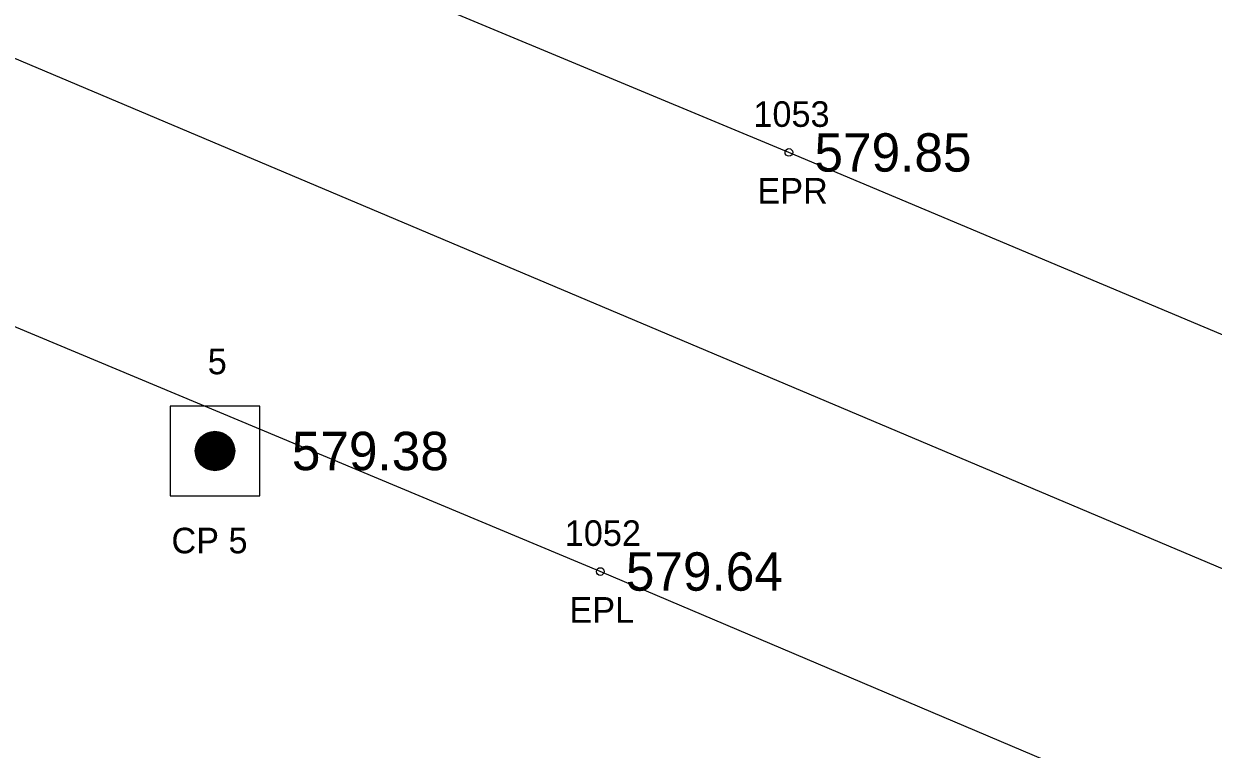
# Model space of a CAD drawing. Extents: x 1664393 to 1667175, y 987029 to 988607.
# Drawn here: x 1665718.92 to 1665765.38, y 987649.18 to 987677.54 of the extents above; entities that cross this region are included whole.
import ezdxf

# ---------------------------------------------------------------- set-up
doc = ezdxf.new("R2010")
doc.units = 0
for name, color, linetype in [('RD_EX_Road', 7, 'Continuous'), ('RD_EX_Road_txCode', 7, 'Continuous'), ('RD_EX_TX_Road_ELEV', 7, 'Continuous'), ('RD_HC_Cl', 7, 'Continuous'), ('RD_HC_Survey', 7, 'Continuous'), ('RD_HC_Survey_ELEV', 7, 'Continuous'), ('RD_HC_Survey_txCode', 7, 'Continuous'), ('RD_SMD_Locator', 7, 'Continuous')]:
    doc.layers.add(name, color=color, linetype=linetype)

msp = doc.modelspace()

# ---------------------------------------------------------------- linework, layer by layer
at = {"layer": 'RD_EX_Road'}
for points in [[(1666163.185, 987497.623), (1666116.595, 987517.386), (1666070.703, 987536.94), (1666024.42, 987556.434), (1665979.015, 987575.668), (1665932.354, 987595.551), (1665886.935, 987614.539), (1665839.872, 987634.254), (1665794.504, 987653.269), (1665748.805, 987672.511), (1665702.363, 987691.865), (1665656.419, 987711.451), (1665610.33, 987731.033), (1665564.854, 987750.933), (1665531.474, 987764.82)], [(1666156.674, 987480.61), (1666109.284, 987500.741), (1666063.55, 987520.043), (1666017.041, 987539.822), (1665971.114, 987559.142), (1665924.884, 987578.792), (1665879.498, 987597.891), (1665833.217, 987617.382), (1665786.906, 987636.812), (1665741.438, 987656.129), (1665695.815, 987675.204), (1665649.264, 987694.848), (1665603.559, 987714.712), (1665558.4, 987733.869), (1665524.706, 987748.932)]]:
    msp.add_lwpolyline(points, dxfattribs=at)
at = {"layer": 'RD_HC_Cl'}
msp.add_line((1666160.052, 987489.414), (1664963.07, 987995.795), dxfattribs=at)
at = {"layer": 'RD_HC_Survey'}
for p, q in [((1665725.763, 987660.39), (1665725.763, 987661.289)), ((1665725.788, 987660.358), (1665725.788, 987661.322)), ((1665725.813, 987660.328), (1665725.813, 987661.351)), ((1665725.837, 987660.302), (1665725.837, 987661.377)), ((1665725.862, 987660.278), (1665725.862, 987661.402)), ((1665725.887, 987660.255), (1665725.887, 987661.424)), ((1665725.912, 987660.235), (1665725.912, 987661.444)), ((1665725.936, 987660.216), (1665725.936, 987661.463)), ((1665725.961, 987660.199), (1665725.961, 987661.48)), ((1665725.986, 987660.183), (1665725.986, 987661.496)), ((1665726.011, 987660.169), (1665726.011, 987661.51)), ((1665726.035, 987660.156), (1665726.035, 987661.524)), ((1665726.06, 987660.143), (1665726.06, 987661.536)), ((1665726.085, 987660.132), (1665726.085, 987661.547)), ((1665726.11, 987660.122), (1665726.11, 987661.557)), ((1665726.134, 987660.113), (1665726.134, 987661.566)), ((1665726.159, 987660.105), (1665726.159, 987661.574)), ((1665726.184, 987660.098), (1665726.184, 987661.582)), ((1665726.209, 987660.091), (1665726.209, 987661.588)), ((1665726.233, 987660.086), (1665726.233, 987661.593)), ((1665726.258, 987660.081), (1665726.258, 987661.598)), ((1665726.283, 987660.077), (1665726.283, 987661.602)), ((1665726.308, 987660.074), (1665726.308, 987661.605)), ((1665726.332, 987660.072), (1665726.332, 987661.607)), ((1665726.357, 987660.071), (1665726.357, 987661.608)), ((1665726.382, 987660.07), (1665726.382, 987661.609)), ((1665726.407, 987660.07), (1665726.407, 987661.609)), ((1665726.431, 987660.071), (1665726.431, 987661.608)), ((1665726.456, 987660.073), (1665726.456, 987661.606)), ((1665726.481, 987660.076), (1665726.481, 987661.603)), ((1665726.506, 987660.079), (1665726.506, 987661.6)), ((1665726.53, 987660.083), (1665726.53, 987661.596)), ((1665726.555, 987660.089), (1665726.555, 987661.591)), ((1665726.58, 987660.094), (1665726.58, 987661.585)), ((1665726.605, 987660.101), (1665726.605, 987661.578)), ((1665726.629, 987660.109), (1665726.629, 987661.57)), ((1665726.654, 987660.118), (1665726.654, 987661.562)), ((1665726.679, 987660.127), (1665726.679, 987661.552)), ((1665726.704, 987660.138), (1665726.704, 987661.541)), ((1665726.728, 987660.15), (1665726.728, 987661.53)), ((1665726.753, 987660.162), (1665726.753, 987661.517)), ((1665726.778, 987660.176), (1665726.778, 987661.503)), ((1665726.803, 987660.192), (1665726.803, 987661.488)), ((1665726.827, 987660.208), (1665726.827, 987661.471)), ((1665726.852, 987660.226), (1665726.852, 987661.453)), ((1665726.877, 987660.246), (1665726.877, 987661.434)), ((1665726.902, 987660.267), (1665726.902, 987661.412)), ((1665726.926, 987660.29), (1665726.926, 987661.389)), ((1665726.951, 987660.315), (1665726.951, 987661.364)), ((1665726.976, 987660.343), (1665726.976, 987661.336)), ((1665727.001, 987660.374), (1665727.001, 987661.305)), ((1665727.025, 987660.409), (1665727.025, 987661.27)), ((1665725.639, 987660.661), (1665725.639, 987661.019)), ((1665725.664, 987660.578), (1665725.664, 987661.101)), ((1665725.689, 987660.518), (1665725.689, 987661.162)), ((1665725.714, 987660.469), (1665725.714, 987661.211)), ((1665725.738, 987660.427), (1665725.738, 987661.252)), ((1665727.05, 987660.448), (1665727.05, 987661.231)), ((1665727.075, 987660.493), (1665727.075, 987661.186)), ((1665727.1, 987660.547), (1665727.1, 987661.132)), ((1665727.124, 987660.617), (1665727.124, 987661.062)), ((1665727.149, 987660.728), (1665727.149, 987660.951))]:
    msp.add_line(p, q, dxfattribs=at)
msp.add_lwpolyline([(1665728.138, 987662.59), (1665724.638, 987662.59), (1665724.638, 987659.09), (1665728.138, 987659.09)], close=True, dxfattribs=at)
msp.add_circle((1665726.388, 987660.84), 0.769, dxfattribs=at)
at = {"layer": 'RD_SMD_Locator'}
for centre in [(1665748.805, 987672.511), (1665726.388, 987660.84), (1665741.438, 987656.129)]:
    msp.add_circle(centre, 0.15, dxfattribs=at)

# ---------------------------------------------------------------- texts
at = {"layer": 'RD_EX_Road_txCode'}
for s, p in [('1053', (1665747.42, 987673.511)), ('EPR', (1665747.577, 987670.511)), ('1052', (1665740.052, 987657.129)), ('EPL', (1665740.233, 987654.129))]:
    msp.add_text(s, height=1, dxfattribs=at).set_placement(p)
at = {"layer": 'RD_EX_TX_Road_ELEV'}
for s, p in [('579.85', (1665749.805, 987671.761)), ('579.64', (1665742.438, 987655.379))]:
    msp.add_text(s, height=1.5, dxfattribs=at).set_placement(p)
at = {"layer": 'RD_HC_Survey_ELEV'}
msp.add_text('579.38', height=1.5, dxfattribs=at).set_placement((1665729.388, 987660.09))
at = {"layer": 'RD_HC_Survey_txCode'}
for s, p in [('5', (1665726.104, 987663.84)), ('CP 5', (1665724.687, 987656.84))]:
    msp.add_text(s, height=1, dxfattribs=at).set_placement(p)

doc.saveas('drawing.dxf')
